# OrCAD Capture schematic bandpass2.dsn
size A
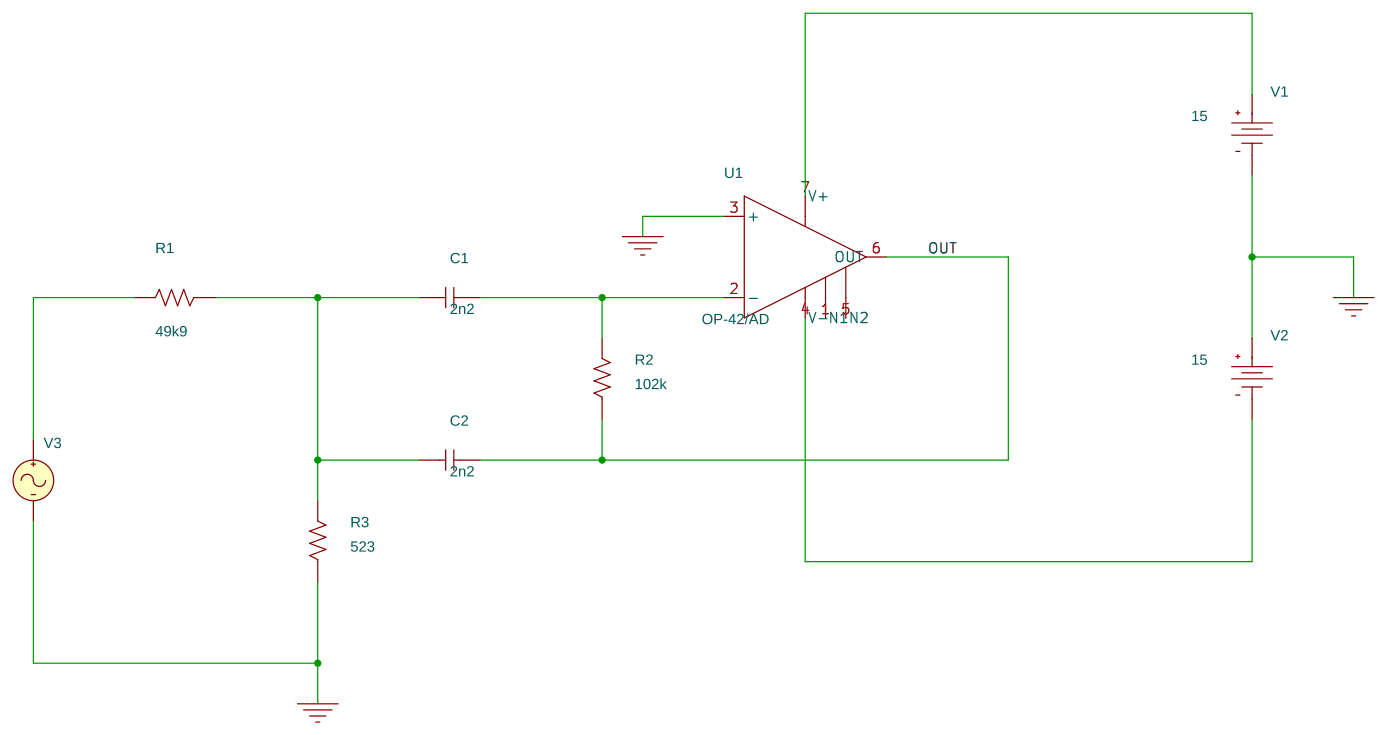
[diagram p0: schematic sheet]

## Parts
C1  2n2  [RAD/CK05]
C2  2n2  [RAD/CK05]
R1  49k9  [AX/RC05]
R2  102k  [AX/RC05]
R3  523  [AX/RC05]
U1  OP-42/AD  [DIP.100/8/W.300/L.425]
V1  VDC
V2  VDC
V3  VAC

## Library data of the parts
C1 C2 = C: TOLERANCE: 5%
R1-R3 = R: TOLERANCE: 1%
U1 = OP-42_AD
V1 V2 = VDC: DC: 15
V3 = VAC

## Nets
0: R3.1 U1.3(+) V1.1(-) V2.0(+) V3.2(-)
OUT: C2.2 R2.1 U1.6(OUT)
N00123: U1.7(V+) V1.0(+)
N00154: U1.4(V-) V2.1(-)
N00166: C1.2 R2.2 U1.2(-)
N00292: C1.1 C2.1 R1.1 R3.2
N00423: R1.2 V3.1(+)

Not connected (* = marked no-connect by the designer): U1 1(N1) 5(N2)
